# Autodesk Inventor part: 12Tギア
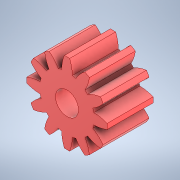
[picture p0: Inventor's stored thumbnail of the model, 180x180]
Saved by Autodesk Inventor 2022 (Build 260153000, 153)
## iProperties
CustomPartVersion: 1
Created: 2024-10
Part Number: 12Tギア
Material: アセタール樹脂、白
Document SubType Name: Modeling
Designer: jsat7
Categories: <?xml version="1.0" encoding="UTF-16"?> <MemberInstance><Categories><FamilyTemplate><FamilyTemplateParameter ValueType="xs:double" Id="1" ObjectReferenceKey="da
Density: 1.425 g/cm^3
Appearance: 滑らか - 白
Author: jsat7
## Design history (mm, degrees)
sketch "Sketch1"
  geometry: C1 r 3.5 at (0, 0)
  constraints: 1 centre point
  dimensions: "d0" = 7 diameter of C1 (= da_da)
extrude "Extrusion1" new body sketch "Sketch1" distance "d1" = 4 (= da_b); taper "d2" = 0 deg
workplane "Work Plane2"
sketch "Sketch2"
  geometry: C1 r 3.5 at (0, 0) reference; C2 r 3 at (0, 0)
  constraints: 1 centre point, 1 coincident
  dimensions: "d3" = 6 diameter of C2 (= da_d)
feature "ピッチ円直径" sketch "Sketch2" dims "d4" = 10, "d5" = 0
workplane "Work Plane8"
workplane "Work Plane9"
feature "平歯車" dims "da_b" = 4, "da_d" = 6, "da_aw" = 11.25, "da_da" = 7, "da_df" = 4.75, "da_dw" = 6, angle "da_beta" = 0 deg, "da_lefttooth" = 0, "da_righttooth" = 0
sketch "スケッチ3"
  geometry: C1 r 1 at (0, 0); 1 further point
  constraints: 1 centre point, 1 coincident
  dimensions: "d49" = 2 diameter of C1
extrude "押し出し2" cut sketch "スケッチ3" distance "d50" = 4; taper "d51" = 0 deg
body "Solid1"
body "Srf1"
other parameters: "d16" = 11.25 (= da_aw), "d17" = 0, "d34" = 15 deg (computed from da_z), "d39" = 0, "d41" = 0, "d43" = 11.25 (= da_aw), "d46" = 11.25 (= da_aw), "d47" = 0, "d48" = 0
